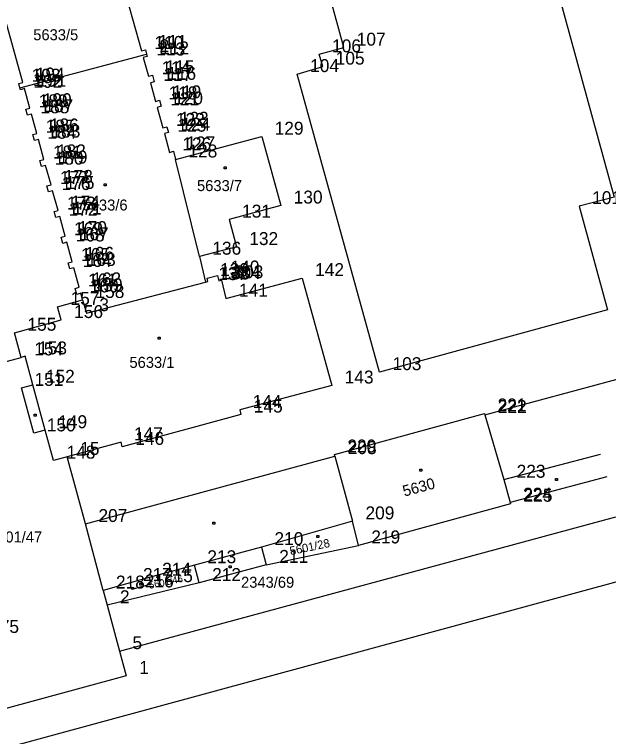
# Model space of a CAD drawing. Extents: x -822293 to -820259, y -1071573 to -1068794.
# Drawn here: x -821254.3 to -821162.5, y -1070329.7 to -1070218.1 of the extents above; entities that cross this region are included whole.
import ezdxf

# ---------------------------------------------------------------- set-up
doc = ezdxf.new("R2010")
doc.units = 0
for name, color, linetype in [('Vrstva 11', 7, 'Continuous'), ('Vrstva 2', 7, 'Continuous'), ('Vrstva 3', 7, 'Continuous'), ('Vrstva 5', 7, 'Continuous'), ('Vrstva 6', 7, 'Continuous'), ('Vrstva 8', 7, 'Continuous'), ('Vrstva 9', 7, 'Continuous')]:
    doc.layers.add(name, color=color, linetype=linetype)

# ---------------------------------------------------------------- blocks, each defined once
blk = doc.blocks.new('Z402')
at = {"layer": 'Vrstva 2'}
for p, q in [((-10, 10), (20, 10)), ((-10, -20), (-10, 10)), ((20, 10), (20, -20)), ((20, -20), (-10, -20))]:
    blk.add_line(p, q, dxfattribs=at)

msp = doc.modelspace()

# ---------------------------------------------------------------- linework, layer by layer
at = {"layer": 'Vrstva 2'}
for p, q in [((-821180.15, -1070178.8), (-821161.7, -1070246.35)), ((-821203.45, -1070223.23), (-821208.34, -1070205.39)), ((-821237.59, -1070213.35), (-821234.7, -1070223.73)), ((-821237.59, -1070213.35), (-821234.7, -1070223.73)), ((-821253.04, -1070228.62), (-821255.9, -1070218.24)), ((-821234.7, -1070223.73), (-821234.1, -1070223.57)), ((-821234.7, -1070223.73), (-821234.1, -1070223.57)), ((-821234.1, -1070223.57), (-821233.91, -1070224.24)), ((-821234.1, -1070223.57), (-821233.82, -1070224.58)), ((-821207.26, -1070224.26), (-821203.45, -1070223.23)), ((-821253.48, -1070229.46), (-821233.91, -1070224.24)), ((-821233.82, -1070224.58), (-821234.42, -1070224.74)), ((-821233.82, -1070224.58), (-821234.42, -1070224.74)), ((-821234.42, -1070224.74), (-821233.61, -1070227.64)), ((-821234.42, -1070224.74), (-821234.322, -1070225.093)), ((-821233.91, -1070224.24), (-821233.82, -1070224.58)), ((-821206.7, -1070226.16), (-821207.26, -1070224.26)), ((-821210.65, -1070227.31), (-821206.7, -1070226.16)), ((-821197.92, -1070273.36), (-821210.65, -1070227.31)), ((-821233.61, -1070227.64), (-821233.01, -1070227.48)), ((-821232.73, -1070228.51), (-821233.32, -1070228.67)), ((-821233.01, -1070227.48), (-821232.73, -1070228.51)), ((-821253.67, -1070228.79), (-821253.04, -1070228.62)), ((-821253.48, -1070229.46), (-821253.67, -1070228.79)), ((-821253.4, -1070229.74), (-821253.48, -1070229.46)), ((-821252.78, -1070229.57), (-821253.4, -1070229.74)), ((-821251.95, -1070232.58), (-821252.78, -1070229.57)), ((-821233.32, -1070228.67), (-821232.53, -1070231.53)), ((-821232.53, -1070231.53), (-821231.93, -1070231.36)), ((-821231.93, -1070231.36), (-821231.67, -1070232.3)), ((-821252.58, -1070232.75), (-821251.95, -1070232.58)), ((-821252.32, -1070233.68), (-821252.58, -1070232.75)), ((-821231.67, -1070232.3), (-821232.27, -1070232.46)), ((-821232.27, -1070232.46), (-821231.39, -1070235.62)), ((-821251.69, -1070233.5), (-821252.32, -1070233.68)), ((-821250.87, -1070236.48), (-821251.69, -1070233.5)), ((-821231.39, -1070235.62), (-821230.79, -1070235.45)), ((-821230.54, -1070236.35), (-821231.14, -1070236.52)), ((-821230.79, -1070235.45), (-821230.54, -1070236.35)), ((-821251.5, -1070236.66), (-821250.87, -1070236.48)), ((-821251.24, -1070237.6), (-821251.5, -1070236.66)), ((-821250.61, -1070237.43), (-821251.24, -1070237.6)), ((-821249.77, -1070240.49), (-821250.61, -1070237.43)), ((-821231.14, -1070236.52), (-821230.39, -1070239.41)), ((-821229.45, -1070240.5), (-821216.13, -1070236.98)), ((-821216.13, -1070236.98), (-821213.19, -1070247.62)), ((-821230.39, -1070239.41), (-821229.78, -1070239.25)), ((-821229.78, -1070239.25), (-821229.45, -1070240.5)), ((-821250.39, -1070240.67), (-821249.77, -1070240.49)), ((-821250.13, -1070241.61), (-821250.39, -1070240.67)), ((-821225.76, -1070255.52), (-821229.45, -1070240.5)), ((-821249.51, -1070241.44), (-821250.13, -1070241.61)), ((-821248.68, -1070244.43), (-821249.51, -1070241.44)), ((-821249.31, -1070244.6), (-821248.68, -1070244.43)), ((-821249.05, -1070245.53), (-821249.31, -1070244.6)), ((-821248.43, -1070245.36), (-821249.05, -1070245.53)), ((-821247.59, -1070248.38), (-821248.43, -1070245.36)), ((-821161.7, -1070246.35), (-821167.08, -1070247.71)), ((-821248.22, -1070248.55), (-821247.59, -1070248.38)), ((-821247.96, -1070249.5), (-821248.22, -1070248.55)), ((-821213.19, -1070247.62), (-821221.16, -1070249.79)), ((-821167.08, -1070247.71), (-821162.69, -1070263.76)), ((-821247.33, -1070249.32), (-821247.96, -1070249.5)), ((-821246.5, -1070252.34), (-821247.33, -1070249.32)), ((-821221.16, -1070249.79), (-821220.05, -1070254.03)), ((-821247.13, -1070252.51), (-821246.5, -1070252.34)), ((-821246.87, -1070253.47), (-821247.13, -1070252.51)), ((-821246.24, -1070253.3), (-821246.87, -1070253.47)), ((-821245.41, -1070256.31), (-821246.24, -1070253.3)), ((-821220.05, -1070254.03), (-821225.76, -1070255.52)), ((-821246.03, -1070256.49), (-821245.41, -1070256.31)), ((-821225.76, -1070255.52), (-821224.83, -1070259.45)), ((-821245.78, -1070257.42), (-821246.03, -1070256.49)), ((-821245.15, -1070257.25), (-821245.78, -1070257.42)), ((-821244.32, -1070260.26), (-821245.15, -1070257.25)), ((-821224.56, -1070258.83), (-821222.94, -1070258.43)), ((-821222.94, -1070258.43), (-821222.74, -1070259.27)), ((-821243.22, -1070264.24), (-821224.83, -1070259.45)), ((-821224.83, -1070259.45), (-821224.44, -1070259.35)), ((-821224.44, -1070259.35), (-821224.56, -1070258.83)), ((-821222.74, -1070259.27), (-821222.34, -1070259.17)), ((-821222.34, -1070259.17), (-821221.65, -1070262)), ((-821221.65, -1070262), (-821209.88, -1070258.83)), ((-821209.88, -1070258.83), (-821205.31, -1070275.42)), ((-821244.95, -1070260.43), (-821244.32, -1070260.26)), ((-821244.69, -1070261.35), (-821244.95, -1070260.43)), ((-821244.07, -1070261.18), (-821244.69, -1070261.35)), ((-821243.81, -1070262.21), (-821244.07, -1070261.18)), ((-821247.67, -1070263.28), (-821243.81, -1070262.21)), ((-821243.81, -1070262.21), (-821243.22, -1070264.24)), ((-821247.11, -1070265.31), (-821247.67, -1070263.28)), ((-821162.69, -1070263.76), (-821197.92, -1070273.36)), ((-821254.32, -1070267.27), (-821247.11, -1070265.31)), ((-821253.28, -1070271.08), (-821254.32, -1070267.27)), ((-821181.65, -1070279.98), (-821143, -1070269.5)), ((-821252.68, -1070270.92), (-821253.28, -1070271.08)), ((-821251.48, -1070275.31), (-821252.68, -1070270.92)), ((-821263.67, -1070273.97), (-821253.28, -1070271.08)), ((-821253.23, -1070275.79), (-821251.48, -1070275.31)), ((-821251.33, -1070282.82), (-821253.23, -1070275.79)), ((-821205.31, -1070275.42), (-821219.53, -1070279.21)), ((-821219.53, -1070279.21), (-821219.35, -1070279.91)), ((-821204.91, -1070286.08), (-821181.7, -1070279.74)), ((-821181.7, -1070279.74), (-821181.65, -1070279.98)), ((-821219.35, -1070279.91), (-821237.67, -1070284.9)), ((-821249.56, -1070282.33), (-821251.33, -1070282.82)), ((-821248.28, -1070287.03), (-821249.56, -1070282.33)), ((-821237.86, -1070284.19), (-821246.17, -1070286.46)), ((-821237.67, -1070284.9), (-821237.86, -1070284.19)), ((-821246.17, -1070286.46), (-821248.28, -1070287.03)), ((-821243.35, -1070296.82), (-821246.17, -1070286.46)), ((-821243.35, -1070296.82), (-821204.84, -1070286.33)), ((-821204.84, -1070286.33), (-821204.91, -1070286.08)), ((-821162.8, -1070289.53), (-821177.75, -1070293.52)), ((-821177.68, -1070293.69), (-821201.2, -1070300.13)), ((-821177.75, -1070293.52), (-821177.68, -1070293.69)), ((-821238.1, -1070316.46), (-821161.41, -1070295.73)), ((-821202.1, -1070296.41), (-821216.16, -1070300.39)), ((-821201.2, -1070300.13), (-821202.1, -1070296.41)), ((-821240.65, -1070307.1), (-821243.35, -1070296.82)), ((-821216.16, -1070300.39), (-821215.42, -1070303.14)), ((-821215.42, -1070303.14), (-821201.2, -1070300.13)), ((-821226.53, -1070303.19), (-821233.51, -1070305.12)), ((-821225.79, -1070305.94), (-821226.53, -1070303.19)), ((-821215.42, -1070303.14), (-821225.79, -1070305.94)), ((-821258.12, -1070332.09), (-821157.32, -1070304.65)), ((-821233.51, -1070305.12), (-821233.23, -1070306.11)), ((-821236.47, -1070305.94), (-821240.65, -1070307.1)), ((-821225.79, -1070305.94), (-821240.03, -1070309.37)), ((-821236.19, -1070306.93), (-821236.47, -1070305.94)), ((-821233.23, -1070306.11), (-821236.19, -1070306.93)), ((-821240.65, -1070307.1), (-821240.03, -1070309.37)), ((-821240.03, -1070309.37), (-821238.1, -1070316.46)), ((-821238.1, -1070316.46), (-821237.06, -1070320.29)), ((-821237.06, -1070320.29), (-821262.67, -1070327.26))]:
    msp.add_line(p, q, dxfattribs=at)
at = {"layer": 'Vrstva 3'}
for p, q in [((-821249.56, -1070282.33), (-821251.48, -1070275.31)), ((-821181.65, -1070279.98), (-821178.75, -1070289.98)), ((-821204.84, -1070286.33), (-821202.1, -1070296.41)), ((-821178.75, -1070289.98), (-821163.81, -1070286.05)), ((-821178.75, -1070289.98), (-821177.75, -1070293.52)), ((-821216.16, -1070300.39), (-821226.53, -1070303.19)), ((-821233.51, -1070305.12), (-821236.47, -1070305.94))]:
    msp.add_line(p, q, dxfattribs=at)
at = {"layer": 'Vrstva 8'}
for p, q in [((-821234.7, -1070223.73), (-821234.7, -1070223.73)), ((-821234.1, -1070223.57), (-821234.1, -1070223.57)), ((-821203.45, -1070223.23), (-821203.45, -1070223.23)), ((-821234.42, -1070224.74), (-821234.42, -1070224.74)), ((-821233.91, -1070224.24), (-821233.91, -1070224.24)), ((-821233.82, -1070224.58), (-821233.82, -1070224.58)), ((-821207.26, -1070224.26), (-821207.26, -1070224.26)), ((-821206.7, -1070226.16), (-821206.7, -1070226.16)), ((-821210.65, -1070227.31), (-821210.65, -1070227.31)), ((-821233.61, -1070227.64), (-821233.61, -1070227.64)), ((-821233.01, -1070227.48), (-821233.01, -1070227.48)), ((-821232.73, -1070228.51), (-821232.73, -1070228.51)), ((-821253.67, -1070228.79), (-821253.67, -1070228.79)), ((-821253.48, -1070229.46), (-821253.48, -1070229.46)), ((-821253.04, -1070228.62), (-821253.04, -1070228.62)), ((-821252.78, -1070229.57), (-821252.78, -1070229.57)), ((-821233.32, -1070228.67), (-821233.32, -1070228.67)), ((-821253.4, -1070229.74), (-821253.4, -1070229.74)), ((-821232.53, -1070231.53), (-821232.53, -1070231.53)), ((-821231.93, -1070231.36), (-821231.93, -1070231.36)), ((-821252.58, -1070232.75), (-821252.58, -1070232.75)), ((-821251.95, -1070232.58), (-821251.95, -1070232.58)), ((-821232.27, -1070232.46), (-821232.27, -1070232.46)), ((-821231.67, -1070232.3), (-821231.67, -1070232.3)), ((-821252.32, -1070233.68), (-821252.32, -1070233.68)), ((-821251.69, -1070233.5), (-821251.69, -1070233.5)), ((-821231.39, -1070235.62), (-821231.39, -1070235.62)), ((-821230.79, -1070235.45), (-821230.79, -1070235.45)), ((-821230.54, -1070236.35), (-821230.54, -1070236.35)), ((-821251.5, -1070236.66), (-821251.5, -1070236.66)), ((-821250.87, -1070236.48), (-821250.87, -1070236.48)), ((-821250.61, -1070237.43), (-821250.61, -1070237.43)), ((-821231.14, -1070236.52), (-821231.14, -1070236.52)), ((-821216.13, -1070236.98), (-821216.13, -1070236.98)), ((-821251.24, -1070237.6), (-821251.24, -1070237.6)), ((-821230.39, -1070239.41), (-821230.39, -1070239.41)), ((-821229.78, -1070239.25), (-821229.78, -1070239.25)), ((-821250.39, -1070240.67), (-821250.39, -1070240.67)), ((-821249.77, -1070240.49), (-821249.77, -1070240.49)), ((-821229.45, -1070240.5), (-821229.45, -1070240.5)), ((-821250.13, -1070241.61), (-821250.13, -1070241.61)), ((-821249.51, -1070241.44), (-821249.51, -1070241.44)), ((-821249.31, -1070244.6), (-821249.31, -1070244.6)), ((-821248.68, -1070244.43), (-821248.68, -1070244.43)), ((-821249.05, -1070245.53), (-821249.05, -1070245.53)), ((-821248.43, -1070245.36), (-821248.43, -1070245.36)), ((-821248.22, -1070248.55), (-821248.22, -1070248.55)), ((-821247.59, -1070248.38), (-821247.59, -1070248.38)), ((-821213.19, -1070247.62), (-821213.19, -1070247.62)), ((-821167.08, -1070247.71), (-821167.08, -1070247.71)), ((-821247.96, -1070249.5), (-821247.96, -1070249.5)), ((-821247.33, -1070249.32), (-821247.33, -1070249.32)), ((-821221.16, -1070249.79), (-821221.16, -1070249.79)), ((-821247.13, -1070252.51), (-821247.13, -1070252.51)), ((-821246.5, -1070252.34), (-821246.5, -1070252.34)), ((-821246.87, -1070253.47), (-821246.87, -1070253.47)), ((-821246.24, -1070253.3), (-821246.24, -1070253.3)), ((-821220.05, -1070254.03), (-821220.05, -1070254.03)), ((-821245.41, -1070256.31), (-821245.41, -1070256.31)), ((-821225.76, -1070255.52), (-821225.76, -1070255.52)), ((-821246.03, -1070256.49), (-821246.03, -1070256.49)), ((-821245.78, -1070257.42), (-821245.78, -1070257.42)), ((-821245.15, -1070257.25), (-821245.15, -1070257.25)), ((-821222.94, -1070258.43), (-821222.94, -1070258.43)), ((-821224.83, -1070259.45), (-821224.83, -1070259.45)), ((-821224.56, -1070258.83), (-821224.56, -1070258.83)), ((-821224.44, -1070259.35), (-821224.44, -1070259.35)), ((-821222.74, -1070259.27), (-821222.74, -1070259.27)), ((-821222.34, -1070259.17), (-821222.34, -1070259.17)), ((-821209.88, -1070258.83), (-821209.88, -1070258.83)), ((-821244.95, -1070260.43), (-821244.95, -1070260.43)), ((-821244.32, -1070260.26), (-821244.32, -1070260.26)), ((-821244.69, -1070261.35), (-821244.69, -1070261.35)), ((-821244.07, -1070261.18), (-821244.07, -1070261.18)), ((-821221.65, -1070262), (-821221.65, -1070262)), ((-821243.81, -1070262.21), (-821243.81, -1070262.21)), ((-821247.67, -1070263.28), (-821247.67, -1070263.28)), ((-821243.22, -1070264.24), (-821243.22, -1070264.24)), ((-821162.69, -1070263.76), (-821162.69, -1070263.76)), ((-821247.11, -1070265.31), (-821247.11, -1070265.31)), ((-821254.32, -1070267.27), (-821254.32, -1070267.27)), ((-821252.68, -1070270.92), (-821252.68, -1070270.92)), ((-821253.28, -1070271.08), (-821253.28, -1070271.08)), ((-821197.92, -1070273.36), (-821197.92, -1070273.36)), ((-821251.48, -1070275.31), (-821251.48, -1070275.31)), ((-821253.23, -1070275.79), (-821253.23, -1070275.79)), ((-821205.31, -1070275.42), (-821205.31, -1070275.42)), ((-821219.53, -1070279.21), (-821219.53, -1070279.21)), ((-821181.7, -1070279.74), (-821181.7, -1070279.74)), ((-821219.35, -1070279.91), (-821219.35, -1070279.91)), ((-821181.65, -1070279.98), (-821181.65, -1070279.98)), ((-821251.33, -1070282.82), (-821251.33, -1070282.82)), ((-821249.56, -1070282.33), (-821249.56, -1070282.33)), ((-821237.86, -1070284.19), (-821237.86, -1070284.19)), ((-821237.67, -1070284.9), (-821237.67, -1070284.9)), ((-821246.17, -1070286.46), (-821246.17, -1070286.46)), ((-821204.91, -1070286.08), (-821204.91, -1070286.08)), ((-821204.84, -1070286.33), (-821204.84, -1070286.33)), ((-821163.81, -1070286.05), (-821163.81, -1070286.05)), ((-821248.28, -1070287.03), (-821248.28, -1070287.03)), ((-821162.8, -1070289.53), (-821162.8, -1070289.53)), ((-821178.75, -1070289.98), (-821178.75, -1070289.98)), ((-821177.75, -1070293.52), (-821177.75, -1070293.52)), ((-821177.68, -1070293.69), (-821177.68, -1070293.69)), ((-821202.1, -1070296.41), (-821202.1, -1070296.41)), ((-821243.35, -1070296.82), (-821243.35, -1070296.82)), ((-821216.16, -1070300.39), (-821216.16, -1070300.39)), ((-821201.2, -1070300.13), (-821201.2, -1070300.13)), ((-821226.53, -1070303.19), (-821226.53, -1070303.19)), ((-821215.42, -1070303.14), (-821215.42, -1070303.14)), ((-821233.51, -1070305.12), (-821233.51, -1070305.12)), ((-821236.47, -1070305.94), (-821236.47, -1070305.94)), ((-821233.23, -1070306.11), (-821233.23, -1070306.11)), ((-821225.79, -1070305.94), (-821225.79, -1070305.94)), ((-821240.65, -1070307.1), (-821240.65, -1070307.1)), ((-821236.19, -1070306.93), (-821236.19, -1070306.93)), ((-821240.03, -1070309.37), (-821240.03, -1070309.37)), ((-821238.1, -1070316.46), (-821238.1, -1070316.46)), ((-821237.06, -1070320.29), (-821237.06, -1070320.29))]:
    msp.add_line(p, q, dxfattribs=at)

# ---------------------------------------------------------------- block references
at = {"layer": 'Vrstva 11', "xscale": 0.01, "yscale": 0.01}
for p in [(-821221.82, -1070241.74), (-821240.35, -1070244.4), (-821232.03, -1070268.05), (-821251.16, -1070279.97), (-821191.61, -1070288.45), (-821170.65, -1070289.92), (-821223.56, -1070296.66), (-821207.5, -1070298.7), (-821221.07, -1070303.4), (-821234.88, -1070306.06)]:
    msp.add_blockref('Z402', p, dxfattribs=at)

# ---------------------------------------------------------------- texts
at = {"layer": 'Vrstva 5'}
for s, p in [('5601/47', (-821258.266, -1070299.68)), ('2343/69', (-821219.326, -1070306.68))]:
    msp.add_text(s, height=1.7, dxfattribs=at).set_placement(p)
msp.add_text('5601/46', height=1.1, rotation=12, dxfattribs=at).set_placement((-821233.436, -1070306.858))
at = {"layer": 'Vrstva 6'}
for s, p in [('5633/5', (-821251.428, -1070222.09)), ('5633/7', (-821226.126, -1070245.4)), ('5633/6', (-821243.806, -1070248.4)), ('5633/1', (-821236.563, -1070272.71))]:
    msp.add_text(s, height=1.7, dxfattribs=at).set_placement(p)
for s, height, rotation, p in [('5630', 1.7, 15, (-821194.097, -1070292.606)), ('5601/28', 1.3, 12, (-821211.655, -1070301.66))]:
    msp.add_text(s, height=height, rotation=rotation, dxfattribs=at).set_placement(p)
at = {"layer": 'Vrstva 9'}
for s, p in [('110', (-821232.7, -1070223.43)), ('111', (-821232.1, -1070223.27)), ('107', (-821201.45, -1070222.93)), ('113', (-821232.42, -1070224.44)), ('2', (-821231.91, -1070223.94)), ('112', (-821231.82, -1070224.28)), ('106', (-821205.26, -1070223.96)), ('105', (-821204.7, -1070225.86)), ('115', (-821231.01, -1070227.18)), ('104', (-821208.65, -1070227.01)), ('194', (-821251.04, -1070228.32)), ('114', (-821231.61, -1070227.34)), ('116', (-821230.73, -1070228.21)), ('193', (-821251.67, -1070228.49)), ('1', (-821251.48, -1070229.16)), ('192', (-821251.4, -1070229.44)), ('191', (-821250.78, -1070229.27)), ('117', (-821231.32, -1070228.37)), ('118', (-821230.53, -1070231.23)), ('119', (-821229.93, -1070231.06)), ('189', (-821250.58, -1070232.45)), ('190', (-821249.95, -1070232.28)), ('121', (-821230.27, -1070232.16)), ('120', (-821229.67, -1070232)), ('188', (-821250.32, -1070233.38)), ('187', (-821249.69, -1070233.2)), ('122', (-821229.39, -1070235.32)), ('123', (-821228.79, -1070235.15)), ('124', (-821228.54, -1070236.05)), ('185', (-821249.5, -1070236.36)), ('186', (-821248.87, -1070236.18)), ('183', (-821248.61, -1070237.13)), ('125', (-821229.14, -1070236.22)), ('129', (-821214.13, -1070236.68)), ('184', (-821249.24, -1070237.3)), ('126', (-821228.39, -1070239.11)), ('127', (-821227.78, -1070238.95)), ('181', (-821248.39, -1070240.37)), ('182', (-821247.77, -1070240.19)), ('128', (-821227.45, -1070240.2)), ('180', (-821248.13, -1070241.31)), ('179', (-821247.51, -1070241.14)), ('177', (-821247.31, -1070244.3)), ('178', (-821246.68, -1070244.13)), ('176', (-821247.05, -1070245.23)), ('175', (-821246.43, -1070245.06)), ('173', (-821246.22, -1070248.25)), ('174', (-821245.59, -1070248.08)), ('130', (-821211.19, -1070247.32)), ('101', (-821165.08, -1070247.41)), ('172', (-821245.96, -1070249.2)), ('171', (-821245.33, -1070249.02)), ('131', (-821219.16, -1070249.49)), ('169', (-821245.13, -1070252.21)), ('170', (-821244.5, -1070252.04)), ('168', (-821244.87, -1070253.17)), ('167', (-821244.24, -1070253)), ('132', (-821218.05, -1070253.73)), ('165', (-821244.03, -1070256.19)), ('166', (-821243.41, -1070256.01)), ('136', (-821223.76, -1070255.22)), ('164', (-821243.78, -1070257.12)), ('163', (-821243.15, -1070256.95)), ('140', (-821220.94, -1070258.13)), ('137', (-821222.83, -1070259.15)), ('139', (-821222.56, -1070258.53)), ('138', (-821222.44, -1070259.05)), ('304', (-821220.74, -1070258.97)), ('303', (-821220.34, -1070258.87)), ('142', (-821207.88, -1070258.53)), ('161', (-821242.95, -1070260.13)), ('162', (-821242.32, -1070259.96)), ('160', (-821242.69, -1070261.05)), ('159', (-821242.07, -1070260.88)), ('141', (-821219.65, -1070261.7)), ('158', (-821241.81, -1070261.91)), ('157', (-821245.67, -1070262.98)), ('3', (-821241.22, -1070263.94)), ('156', (-821245.11, -1070265.01)), ('155', (-821252.32, -1070266.97)), ('153', (-821250.68, -1070270.62)), ('154', (-821251.28, -1070270.78)), ('103', (-821195.92, -1070273.06)), ('152', (-821249.48, -1070275.01)), ('143', (-821203.31, -1070275.12)), ('151', (-821251.23, -1070275.49)), ('144', (-821217.53, -1070278.91)), ('145', (-821217.35, -1070279.61)), ('221', (-821179.7, -1070279.44)), ('222', (-821179.65, -1070279.68)), ('150', (-821249.33, -1070282.52)), ('149', (-821247.56, -1070282.03)), ('147', (-821235.86, -1070283.89)), ('146', (-821235.67, -1070284.6)), ('15', (-821244.17, -1070286.16)), ('220', (-821202.91, -1070285.78)), ('208', (-821202.84, -1070286.03)), ('148', (-821246.28, -1070286.73)), ('223', (-821176.75, -1070289.68)), ('224', (-821175.75, -1070293.22)), ('225', (-821175.68, -1070293.39)), ('209', (-821200.1, -1070296.11)), ('207', (-821241.35, -1070296.52)), ('210', (-821214.16, -1070300.09)), ('219', (-821199.2, -1070299.83)), ('213', (-821224.53, -1070302.89)), ('211', (-821213.42, -1070302.84)), ('214', (-821231.51, -1070304.82)), ('217', (-821234.47, -1070305.64)), ('215', (-821231.23, -1070305.81)), ('212', (-821223.79, -1070305.64)), ('218', (-821238.65, -1070306.8)), ('216', (-821234.19, -1070306.63)), ('2', (-821238.03, -1070309.07)), ('75', (-821256.6, -1070313.67)), ('5', (-821236.1, -1070316.16)), ('1', (-821235.06, -1070319.99))]:
    msp.add_text(s, height=2, dxfattribs=at).set_placement(p)

doc.saveas('drawing.dxf')
